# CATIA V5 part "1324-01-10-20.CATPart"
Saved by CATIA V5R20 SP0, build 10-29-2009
Part number: 1324-01-10-20
Revision: ANY
Definition: UNKNOWN
Nomenclature: 1324-01-10-20
Source: Unknown
Bounding box of the stored display mesh (mm): x -100 to 10, y -10 to 10, z 0 to 7.8
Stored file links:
  C:\Users\Utente\Desktop\IO LAVORO\3D X SITO CF\CUMSA\3D files SL.602008\SL 602008\1324-01-10-20.CATPart
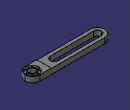
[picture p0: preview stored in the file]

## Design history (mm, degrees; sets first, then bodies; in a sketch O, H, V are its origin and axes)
Body1 "Redondeo2" (main body)
  Solid1: solid without history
